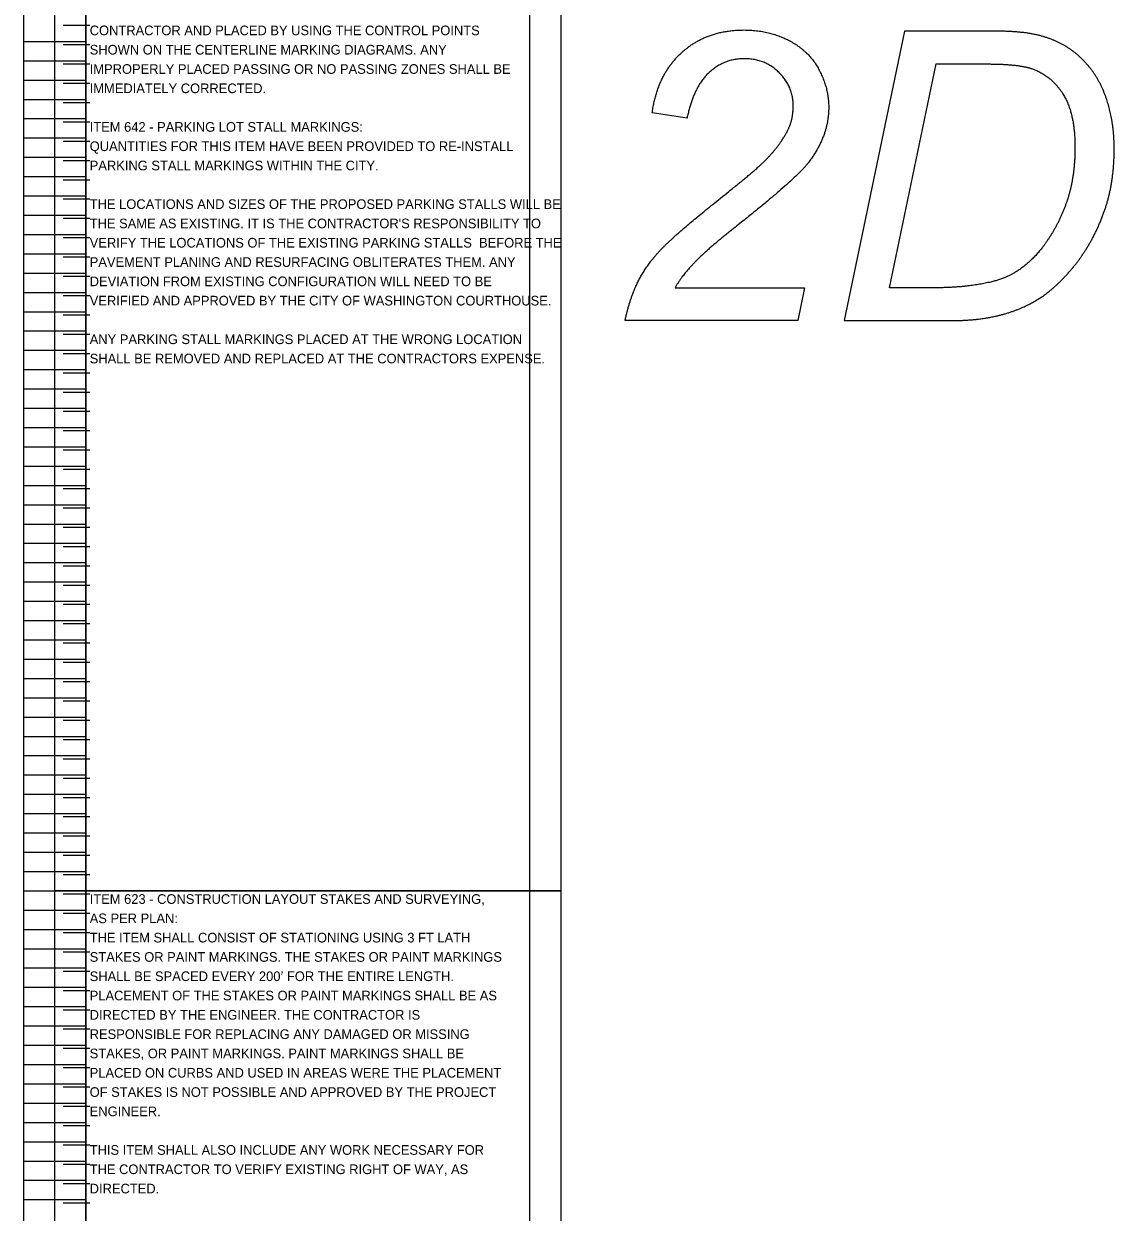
# Model space of a CAD drawing. Extents: x 12522 to 13018, y 1124 to 1902.
# Drawn here: x 12521.92 to 12537.74, y 1683.85 to 1701.09 of the extents above; entities that cross this region are included whole.
import ezdxf

# ---------------------------------------------------------------- set-up
doc = ezdxf.new("R2010")
doc.units = 0
doc.layers.add('SC_Scratch1', color=7, linetype='Continuous')
doc.layers.add('SH_Text', color=7, linetype='Continuous')

msp = doc.modelspace()

# ---------------------------------------------------------------- linework, layer by layer
at = {"layer": 'SC_Scratch1'}
for p, q in [((12521.919, 1688.511), (12521.919, 1708.671)), ((12522.819, 1688.511), (12522.819, 1708.671)), ((12522.819, 1708.671), (12522.819, 1688.511)), ((12522.876, 1701.061), (12522.492, 1701.061)), ((12521.919, 1700.831), (12522.819, 1700.831)), ((12522.876, 1700.781), (12522.492, 1700.781)), ((12521.919, 1700.551), (12522.819, 1700.551)), ((12522.876, 1700.501), (12522.492, 1700.501)), ((12521.919, 1700.271), (12522.819, 1700.271)), ((12522.876, 1700.221), (12522.492, 1700.221)), ((12521.919, 1699.991), (12522.819, 1699.991)), ((12522.876, 1699.941), (12522.492, 1699.941)), ((12521.919, 1699.711), (12522.819, 1699.711)), ((12522.876, 1699.661), (12522.492, 1699.661)), ((12531.543, 1699.719), (12531.037, 1699.794)), ((12521.919, 1699.431), (12522.819, 1699.431)), ((12522.876, 1699.381), (12522.492, 1699.381)), ((12521.919, 1699.151), (12522.819, 1699.151)), ((12522.876, 1699.101), (12522.492, 1699.101)), ((12521.919, 1698.871), (12522.819, 1698.871)), ((12522.876, 1698.821), (12522.492, 1698.821)), ((12521.919, 1698.591), (12522.819, 1698.591)), ((12522.876, 1698.541), (12522.492, 1698.541)), ((12521.919, 1698.311), (12522.819, 1698.311)), ((12522.876, 1698.261), (12522.492, 1698.261)), ((12521.919, 1698.031), (12522.819, 1698.031)), ((12522.876, 1697.981), (12522.492, 1697.981)), ((12521.919, 1697.751), (12522.819, 1697.751)), ((12522.876, 1697.701), (12522.492, 1697.701)), ((12521.919, 1697.471), (12522.819, 1697.471)), ((12522.876, 1697.421), (12522.492, 1697.421)), ((12521.919, 1697.191), (12522.819, 1697.191)), ((12522.876, 1697.141), (12522.492, 1697.141)), ((12521.919, 1696.911), (12522.819, 1696.911)), ((12522.876, 1696.861), (12522.492, 1696.861)), ((12521.919, 1696.631), (12522.819, 1696.631)), ((12522.876, 1696.581), (12522.492, 1696.581)), ((12521.919, 1696.351), (12522.819, 1696.351)), ((12522.876, 1696.301), (12522.492, 1696.301)), ((12521.919, 1696.071), (12522.819, 1696.071)), ((12522.876, 1696.021), (12522.492, 1696.021)), ((12521.919, 1695.791), (12522.819, 1695.791)), ((12522.876, 1695.741), (12522.492, 1695.741)), ((12521.919, 1695.511), (12522.819, 1695.511)), ((12522.876, 1695.461), (12522.492, 1695.461)), ((12521.919, 1695.231), (12522.819, 1695.231)), ((12522.876, 1695.181), (12522.492, 1695.181)), ((12521.919, 1694.951), (12522.819, 1694.951)), ((12522.876, 1694.901), (12522.492, 1694.901)), ((12521.919, 1694.671), (12522.819, 1694.671)), ((12522.876, 1694.621), (12522.492, 1694.621)), ((12521.919, 1694.391), (12522.819, 1694.391)), ((12522.876, 1694.341), (12522.492, 1694.341)), ((12521.919, 1694.111), (12522.819, 1694.111)), ((12522.876, 1694.061), (12522.492, 1694.061)), ((12521.919, 1693.831), (12522.819, 1693.831)), ((12522.876, 1693.781), (12522.492, 1693.781)), ((12521.919, 1693.551), (12522.819, 1693.551)), ((12522.876, 1693.501), (12522.492, 1693.501)), ((12521.919, 1693.271), (12522.819, 1693.271)), ((12522.876, 1693.221), (12522.492, 1693.221)), ((12521.919, 1692.991), (12522.819, 1692.991)), ((12522.876, 1692.941), (12522.492, 1692.941)), ((12521.919, 1692.711), (12522.819, 1692.711)), ((12522.876, 1692.661), (12522.492, 1692.661)), ((12521.919, 1692.431), (12522.819, 1692.431)), ((12522.876, 1692.381), (12522.492, 1692.381)), ((12521.919, 1692.151), (12522.819, 1692.151)), ((12522.876, 1692.101), (12522.492, 1692.101)), ((12521.919, 1691.871), (12522.819, 1691.871)), ((12522.876, 1691.821), (12522.492, 1691.821)), ((12521.919, 1691.591), (12522.819, 1691.591)), ((12522.876, 1691.541), (12522.492, 1691.541)), ((12521.919, 1691.311), (12522.819, 1691.311)), ((12522.876, 1691.261), (12522.492, 1691.261)), ((12521.919, 1691.031), (12522.819, 1691.031)), ((12522.876, 1690.981), (12522.492, 1690.981)), ((12521.919, 1690.751), (12522.819, 1690.751)), ((12522.876, 1690.701), (12522.492, 1690.701)), ((12521.919, 1690.471), (12522.819, 1690.471)), ((12522.876, 1690.421), (12522.492, 1690.421)), ((12521.919, 1690.191), (12522.819, 1690.191)), ((12522.876, 1690.141), (12522.492, 1690.141)), ((12521.919, 1689.911), (12522.819, 1689.911)), ((12522.876, 1689.861), (12522.492, 1689.861)), ((12521.919, 1689.631), (12522.819, 1689.631)), ((12522.876, 1689.581), (12522.492, 1689.581)), ((12521.919, 1689.351), (12522.819, 1689.351)), ((12522.876, 1689.301), (12522.492, 1689.301)), ((12521.919, 1689.071), (12522.819, 1689.071)), ((12522.876, 1689.021), (12522.492, 1689.021)), ((12521.919, 1688.791), (12522.819, 1688.791)), ((12522.876, 1688.741), (12522.492, 1688.741)), ((12521.919, 1688.511), (12522.819, 1688.511)), ((12521.919, 1668.351), (12521.919, 1688.511)), ((12521.919, 1688.511), (12522.819, 1688.511)), ((12522.876, 1688.461), (12522.492, 1688.461)), ((12522.819, 1668.351), (12522.819, 1688.511)), ((12522.819, 1688.511), (12522.819, 1668.351)), ((12521.919, 1688.231), (12522.819, 1688.231)), ((12522.876, 1688.181), (12522.492, 1688.181)), ((12521.919, 1687.951), (12522.819, 1687.951)), ((12522.876, 1687.901), (12522.492, 1687.901)), ((12521.919, 1687.671), (12522.819, 1687.671)), ((12522.876, 1687.621), (12522.492, 1687.621)), ((12521.919, 1687.391), (12522.819, 1687.391)), ((12522.876, 1687.341), (12522.492, 1687.341)), ((12521.919, 1687.111), (12522.819, 1687.111)), ((12522.876, 1687.061), (12522.492, 1687.061)), ((12521.919, 1686.831), (12522.819, 1686.831)), ((12522.876, 1686.781), (12522.492, 1686.781)), ((12521.919, 1686.551), (12522.819, 1686.551)), ((12522.876, 1686.501), (12522.492, 1686.501)), ((12521.919, 1686.271), (12522.819, 1686.271)), ((12522.876, 1686.221), (12522.492, 1686.221)), ((12521.919, 1685.991), (12522.819, 1685.991)), ((12522.876, 1685.941), (12522.492, 1685.941)), ((12521.919, 1685.711), (12522.819, 1685.711)), ((12522.876, 1685.661), (12522.492, 1685.661)), ((12521.919, 1685.431), (12522.819, 1685.431)), ((12522.876, 1685.381), (12522.492, 1685.381)), ((12521.919, 1685.151), (12522.819, 1685.151)), ((12522.876, 1685.101), (12522.492, 1685.101)), ((12521.919, 1684.871), (12522.819, 1684.871)), ((12522.876, 1684.821), (12522.492, 1684.821)), ((12521.919, 1684.591), (12522.819, 1684.591)), ((12522.876, 1684.541), (12522.492, 1684.541)), ((12521.919, 1684.311), (12522.819, 1684.311)), ((12522.876, 1684.261), (12522.492, 1684.261)), ((12521.919, 1684.031), (12522.819, 1684.031)), ((12522.876, 1683.981), (12522.492, 1683.981))]:
    msp.add_line(p, q, dxfattribs=at)
for points in [[(12522.369, 1708.671), (12529.709, 1708.671), (12529.709, 1688.511), (12522.369, 1688.511)], [(12522.819, 1708.671), (12529.259, 1708.671), (12529.259, 1688.511), (12522.819, 1688.511)], [(12522.369, 1688.511), (12529.709, 1688.511), (12529.709, 1668.351), (12522.369, 1668.351)], [(12522.819, 1688.511), (12529.259, 1688.511), (12529.259, 1668.351), (12522.819, 1668.351)]]:
    msp.add_lwpolyline(points, close=True, dxfattribs=at)
for points in [[(12535.966, 1700.981), (12534.699, 1700.981), (12533.822, 1696.781), (12535.335, 1696.781)], [(12535.147, 1697.258), (12534.481, 1697.258), (12535.159, 1700.504), (12535.903, 1700.504)], [(12531.369, 1697.258), (12533.249, 1697.258), (12533.149, 1696.781), (12530.643, 1696.781)]]:
    msp.add_lwpolyline(points, dxfattribs=at)
for points in [[(12531.471, 1700.675), (12531.831, 1700.997), (12532.366, 1700.997)], [(12532.366, 1700.997), (12532.724, 1700.997), (12533.015, 1700.848)], [(12533.015, 1700.848), (12533.306, 1700.699), (12533.452, 1700.43)], [(12536.663, 1700.915), (12536.422, 1700.981), (12535.966, 1700.981)], [(12537.25, 1700.598), (12537.007, 1700.826), (12536.663, 1700.915)], [(12531.037, 1699.794), (12531.111, 1700.352), (12531.471, 1700.675)], [(12532.374, 1700.581), (12532.079, 1700.581), (12531.858, 1700.376)], [(12532.878, 1700.379), (12532.673, 1700.581), (12532.374, 1700.581)], [(12535.903, 1700.504), (12536.334, 1700.504), (12536.538, 1700.438)], [(12537.617, 1700.03), (12537.494, 1700.371), (12537.25, 1700.598)], [(12531.858, 1700.376), (12531.637, 1700.171), (12531.543, 1699.719)], [(12533.083, 1699.888), (12533.083, 1700.177), (12532.878, 1700.379)], [(12533.452, 1700.43), (12533.598, 1700.161), (12533.598, 1699.874)], [(12536.538, 1700.438), (12536.814, 1700.349), (12536.992, 1700.076)], [(12536.992, 1700.076), (12537.171, 1699.802), (12537.171, 1699.292)], [(12537.74, 1699.265), (12537.74, 1699.689), (12537.617, 1700.03)], [(12533.017, 1699.57), (12533.083, 1699.716), (12533.083, 1699.888)], [(12533.598, 1699.874), (12533.598, 1699.456), (12533.3, 1699.069)], [(12532.704, 1699.132), (12532.919, 1699.356), (12533.017, 1699.57)], [(12537.171, 1699.292), (12537.171, 1698.834), (12537.04, 1698.474)], [(12532.148, 1698.654), (12532.555, 1698.978), (12532.704, 1699.132)], [(12537.587, 1698.341), (12537.74, 1698.758), (12537.74, 1699.265)], [(12533.3, 1699.069), (12533.117, 1698.829), (12532.223, 1698.122)], [(12531.242, 1697.891), (12531.477, 1698.119), (12532.148, 1698.654)], [(12537.04, 1698.474), (12536.909, 1698.115), (12536.691, 1697.834)], [(12537.186, 1697.607), (12537.434, 1697.924), (12537.587, 1698.341)], [(12532.223, 1698.122), (12531.839, 1697.819), (12531.651, 1697.624)], [(12530.865, 1697.41), (12531.007, 1697.664), (12531.242, 1697.891)], [(12536.691, 1697.834), (12536.525, 1697.622), (12536.321, 1697.493)], [(12531.651, 1697.624), (12531.463, 1697.43), (12531.369, 1697.258)], [(12536.667, 1697.112), (12536.938, 1697.291), (12537.186, 1697.607)], [(12530.643, 1696.781), (12530.724, 1697.156), (12530.865, 1697.41)], [(12536.321, 1697.493), (12536.166, 1697.393), (12535.948, 1697.341)], [(12535.948, 1697.341), (12535.597, 1697.258), (12535.147, 1697.258)], [(12536.026, 1696.847), (12536.396, 1696.933), (12536.667, 1697.112)], [(12535.335, 1696.781), (12535.745, 1696.781), (12536.026, 1696.847)]]:
    msp.add_open_spline(points, degree=2, dxfattribs=at)

# ---------------------------------------------------------------- texts
at = {"layer": 'SH_Text'}
for s, p in [('CONTRACTOR AND PLACED BY USING THE CONTROL POINTS ', (12522.876, 1700.921)), ('SHOWN ON THE CENTERLINE MARKING DIAGRAMS. ANY ', (12522.876, 1700.641)), ('IMPROPERLY PLACED PASSING OR NO PASSING ZONES SHALL BE ', (12522.876, 1700.361)), ('IMMEDIATELY CORRECTED. ', (12522.876, 1700.081)), ('ITEM 642 - PARKING LOT STALL MARKINGS:', (12522.876, 1699.521)), ('QUANTITIES FOR THIS ITEM HAVE BEEN PROVIDED TO RE-INSTALL ', (12522.876, 1699.241)), ('PARKING STALL MARKINGS WITHIN THE CITY.', (12522.876, 1698.961)), ('THE LOCATIONS AND SIZES OF THE PROPOSED PARKING STALLS WILL BE ', (12522.876, 1698.401)), ("THE SAME AS EXISTING. IT IS THE CONTRACTOR'S RESPONSIBILITY TO ", (12522.876, 1698.121)), ('VERIFY THE LOCATIONS OF THE EXISTING PARKING STALLS  BEFORE THE ', (12522.876, 1697.841)), ('PAVEMENT PLANING AND RESURFACING OBLITERATES THEM. ANY ', (12522.876, 1697.561)), ('DEVIATION FROM EXISTING CONFIGURATION WILL NEED TO BE ', (12522.876, 1697.281)), ('VERIFIED AND APPROVED BY THE CITY OF WASHINGTON COURTHOUSE. ', (12522.876, 1697.001)), ('ANY PARKING STALL MARKINGS PLACED AT THE WRONG LOCATION ', (12522.876, 1696.441)), ('SHALL BE REMOVED AND REPLACED AT THE CONTRACTORS EXPENSE.', (12522.876, 1696.161)), ('ITEM 623 - CONSTRUCTION LAYOUT STAKES AND SURVEYING, ', (12522.876, 1688.321)), ('AS PER PLAN:', (12522.876, 1688.041)), ('THE ITEM SHALL CONSIST OF STATIONING USING 3 FT LATH ', (12522.876, 1687.761)), ('STAKES OR PAINT MARKINGS. THE STAKES OR PAINT MARKINGS ', (12522.876, 1687.481)), ('SHALL BE SPACED EVERY 200’ FOR THE ENTIRE LENGTH. ', (12522.876, 1687.201)), ('PLACEMENT OF THE STAKES OR PAINT MARKINGS SHALL BE AS ', (12522.876, 1686.921)), ('DIRECTED BY THE ENGINEER. THE CONTRACTOR IS ', (12522.876, 1686.641)), ('RESPONSIBLE FOR REPLACING ANY DAMAGED OR MISSING ', (12522.876, 1686.361)), ('STAKES, OR PAINT MARKINGS. PAINT MARKINGS SHALL BE ', (12522.876, 1686.081)), ('PLACED ON CURBS AND USED IN AREAS WERE THE PLACEMENT ', (12522.876, 1685.801)), ('OF STAKES IS NOT POSSIBLE AND APPROVED BY THE PROJECT ', (12522.876, 1685.521)), ('ENGINEER.  ', (12522.876, 1685.241)), ('THIS ITEM SHALL ALSO INCLUDE ANY WORK NECESSARY FOR ', (12522.876, 1684.681)), ('THE CONTRACTOR TO VERIFY EXISTING RIGHT OF WAY, AS ', (12522.876, 1684.401)), ('DIRECTED.', (12522.876, 1684.121))]:
    msp.add_text(s, height=0.14, dxfattribs=at).set_placement(p)

doc.saveas('drawing.dxf')
